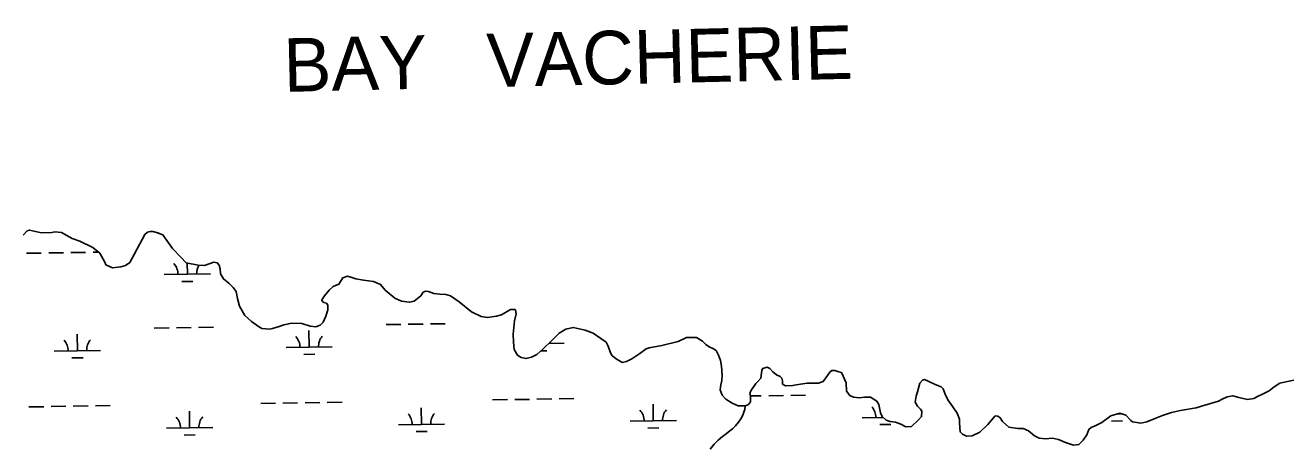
# Model space of a CAD drawing. Extents: x 3812694 to 3850888, y 319753 to 345638.
# Drawn here: x 3822925 to 3825660, y 332970 to 333885 of the extents above; entities that cross this region are included whole.
import ezdxf

# ---------------------------------------------------------------- set-up
doc = ezdxf.new("R2010")
doc.units = 0
for name, color, linetype in [('V-RIVR-IDEN', 7, 'Continuous'), ('V-TOPO-SHOR', 7, 'Continuous'), ('V-WETL-SWMP', 7, 'Continuous')]:
    doc.layers.add(name, color=color, linetype=linetype)

msp = doc.modelspace()

# ---------------------------------------------------------------- linework, layer by layer
at = {"layer": 'V-TOPO-SHOR'}
for points in [[(3823704.4, 333311.1), (3823694.2, 333323.5), (3823679.2, 333330.3), (3823657.3, 333332.5), (3823640.9, 333335.9), (3823630, 333339.4), (3823622.4, 333341.5), (3823612.2, 333338.1), (3823603.9, 333324.4), (3823591.6, 333319), (3823582.7, 333311.5), (3823573, 333299.2), (3823566.9, 333290.3), (3823568.2, 333286.9), (3823571.6, 333284.8), (3823577.1, 333282.8), (3823579.8, 333278.7), (3823579.8, 333268.4), (3823575.6, 333254.7), (3823570.1, 333241.7), (3823563.3, 333235.6), (3823553.7, 333231.5), (3823542, 333232.9), (3823523.6, 333239.1), (3823502.4, 333239.9), (3823484.6, 333235.8), (3823475, 333232.4), (3823459.9, 333228.4), (3823454.4, 333227), (3823437.3, 333228.5), (3823429.8, 333232.6), (3823414.8, 333243.6), (3823400.5, 333256.6), (3823388.9, 333276.5), (3823384.2, 333292.9), (3823381.5, 333308), (3823375.4, 333316.9), (3823366.5, 333325.8), (3823354.2, 333335.5), (3823347.4, 333346.4), (3823346.7, 333357.4), (3823344.7, 333365.6), (3823340.6, 333370.4), (3823333.1, 333371.8), (3823313.2, 333364.3), (3823299.6, 333365), (3823273.6, 333370.6), (3823262, 333382.3), (3823243.6, 333401.5), (3823223.1, 333431), (3823209.4, 333435.8), (3823201.2, 333437.9), (3823195.1, 333437.9), (3823189.6, 333436.5), (3823184.1, 333431.8), (3823161.4, 333390.1), (3823151.1, 333371), (3823142.2, 333364.8), (3823131.9, 333361.5), (3823114.1, 333359.5), (3823099.8, 333366.3), (3823097, 333371.8), (3823086.8, 333391), (3823071.1, 333403.4), (3823043.1, 333417.2), (3823026.7, 333423.4), (3823015.1, 333429.6), (3823003.5, 333436.4), (3822989.1, 333437.2), (3822982.3, 333435.8), (3822960.4, 333435.2), (3822934.4, 333441.4), (3822928.9, 333439.4), (3822920.7, 333430.5)], [(3824666.6, 333133.7), (3824661.8, 333126.2), (3824652.2, 333113.2), (3824641.9, 333109.8), (3824617.3, 333109.9), (3824594, 333106.5), (3824586.5, 333104.5), (3824570.7, 333103.9), (3824564.6, 333108), (3824564.6, 333114.8), (3824562.6, 333121), (3824559.2, 333124.4), (3824551, 333127.9), (3824543.5, 333134), (3824536.6, 333141.6), (3824531.2, 333144.3), (3824521.6, 333141.6), (3824519.5, 333138.2), (3824518.8, 333131.4), (3824517.4, 333120.4), (3824511.2, 333113.6), (3824506.4, 333108.8), (3824495.4, 333093.1), (3824493.4, 333087.7), (3824494.7, 333082.2), (3824494.7, 333080.8), (3824494.7, 333069.2), (3824490.6, 333063.7), (3824483.7, 333061), (3824468.6, 333060.4), (3824455, 333066.6), (3824441.3, 333075.5), (3824433.8, 333083.8), (3824429.1, 333095.4), (3824430.5, 333106.3), (3824432.6, 333115.9), (3824433.3, 333126.9), (3824432, 333146.7), (3824430, 333159), (3824425.9, 333170.7), (3824420.4, 333180.3), (3824415, 333184.4), (3824405.4, 333188.5), (3824398.6, 333193.3), (3824391.1, 333200.9), (3824378.1, 333208.5), (3824356.2, 333208.5), (3824338.4, 333199.7), (3824302.8, 333191.6), (3824275.4, 333186.2), (3824269.2, 333184.2), (3824255.5, 333173.9), (3824238.4, 333162.4), (3824226.7, 333156.9), (3824217.8, 333154.9), (3824208.3, 333159.7), (3824195.3, 333169.3), (3824191.9, 333175.5), (3824187.1, 333189.9), (3824182.4, 333198.8), (3824170.8, 333206.4), (3824154.4, 333218), (3824137.3, 333224.9), (3824111.3, 333230.5), (3824094.9, 333227.1), (3824080.5, 333218.3), (3824064, 333201.2), (3824046.2, 333184.2), (3824032.5, 333171.9), (3824020.8, 333166.4), (3824009.2, 333163.1), (3823998.2, 333165.1), (3823990.7, 333170.6), (3823983.2, 333183), (3823981.9, 333198.7), (3823981.3, 333215.8), (3823982.7, 333230.2), (3823984.1, 333244.6), (3823987.6, 333260.3), (3823986.2, 333267.8), (3823985.5, 333269.2), (3823975.3, 333269.2), (3823956.1, 333257.7), (3823945.1, 333254.9), (3823926, 333252.3), (3823911.6, 333254.4), (3823891.1, 333264), (3823864.5, 333286), (3823845.4, 333299), (3823835.8, 333301.8), (3823822.8, 333302.5), (3823809.8, 333303.9), (3823798.2, 333308.1), (3823792, 333308.8), (3823786.5, 333306.8), (3823781, 333298.6), (3823766.6, 333287.7), (3823757.1, 333284.9), (3823739.3, 333287.1), (3823724.9, 333293.9), (3823704.4, 333311.1)], [(3825671, 333116.2), (3825653.9, 333112.8), (3825640.9, 333109.5), (3825628.5, 333102), (3825617.6, 333093.1), (3825603.2, 333086.3), (3825593.6, 333081.5), (3825584.7, 333076.8), (3825571, 333074.8), (3825551.8, 333078.9), (3825538.9, 333082.4), (3825527.2, 333080.4), (3825516.3, 333074.9), (3825508, 333070.9), (3825478.6, 333062.1), (3825459.4, 333056.6), (3825425.9, 333050.6), (3825406, 333046.5), (3825386.8, 333039.8), (3825372.4, 333034.3), (3825352.6, 333026.2), (3825340.2, 333023.5), (3825321.8, 333026.3), (3825318.4, 333029), (3825307.5, 333040.7), (3825294.5, 333044.8), (3825275.3, 333039.4), (3825255.4, 333024.4), (3825241, 333017.6), (3825232.1, 333013.6), (3825227.3, 333009.5), (3825223.2, 332997.8), (3825214.9, 332986.2), (3825206, 332976.7), (3825194.4, 332975.4), (3825176.6, 332981.6), (3825161.6, 332987.8), (3825148.6, 332990.5), (3825133.5, 332989.2), (3825119.8, 332990.6), (3825109.6, 332995.5), (3825096.6, 333006.4), (3825085, 333012), (3825074, 333012), (3825054.2, 333014.8), (3825040.6, 333026.5), (3825035.1, 333034.7), (3825030.3, 333038.1), (3825024.9, 333038.8), (3825008.4, 333020.4), (3824991.2, 333004), (3824974.8, 332995.9), (3824962.5, 332995.2), (3824953.6, 332999.4), (3824948.8, 333004.2), (3824947.5, 333024), (3824947.5, 333032.2), (3824942.1, 333044.6), (3824933.2, 333058.3), (3824922.3, 333074), (3824916.2, 333085.7), (3824912.1, 333097.3), (3824907.4, 333102.1), (3824894.4, 333107), (3824879.4, 333114.5), (3824871.8, 333118), (3824867, 333116.6), (3824861.5, 333109.8), (3824856.7, 333091.3), (3824853.9, 333081.8), (3824851.8, 333068.8), (3824856.6, 333059.9), (3824862.7, 333053.7), (3824866.2, 333048.9), (3824865.4, 333037.3), (3824858.6, 333030.4), (3824843.5, 333016.1), (3824831.2, 333015.5), (3824820.2, 333021), (3824808.6, 333025.1), (3824797, 333026.5), (3824788.8, 333030), (3824779.9, 333037.5), (3824776.5, 333045.7), (3824772.5, 333063.6), (3824768.4, 333071.1), (3824754.7, 333079.3), (3824741.7, 333079.4), (3824730.8, 333078), (3824717.8, 333079.5), (3824710.2, 333082.9), (3824702.8, 333092.5), (3824702.1, 333110.3), (3824691.9, 333132.9), (3824686.5, 333134.3), (3824677.6, 333137.1), (3824670.7, 333137.1), (3824666.6, 333133.7)], [(3824483.7, 333061), (3824482.8, 333053), (3824481.6, 333049), (3824479.9, 333044.9), (3824478.1, 333040.7), (3824474.2, 333032.9), (3824469, 333025.1), (3824462.7, 333017.2), (3824455.9, 333010.8), (3824450.5, 333006.4), (3824442.6, 333000.4), (3824434.3, 332994.3), (3824425.1, 332986.4), (3824416.1, 332977.5), (3824407.8, 332967)]]:
    msp.add_lwpolyline(points, dxfattribs=at)
at = {"layer": 'V-WETL-SWMP'}
for p, q in [((3822927.8, 333391.1), (3822959.8, 333391.6)), ((3822975.8, 333391.8), (3823007.8, 333392.3)), ((3823023.8, 333392.5), (3823055.8, 333393)), ((3823071.8, 333393.3), (3823083.8, 333393.4)), ((3823275.9, 333345.6), (3823275.5, 333370.2)), ((3823225.9, 333344.8), (3823325.9, 333346.4)), ((3823264.1, 333330), (3823288.1, 333330.3)), ((3823037.9, 333180.1), (3823037.3, 333216.1)), ((3823204.2, 333229.1), (3823236.2, 333229.6)), ((3823252.2, 333229.8), (3823284.2, 333230.3)), ((3823300.2, 333230.5), (3823332.2, 333231)), ((3823539.7, 333187.7), (3823539.2, 333223.7)), ((3823706.1, 333236.7), (3823738.1, 333237.1)), ((3823754.1, 333237.4), (3823786.1, 333237.9)), ((3823802.1, 333238.1), (3823834.1, 333238.6)), ((3823489.7, 333187), (3823589.7, 333188.5)), ((3824058.1, 333195.6), (3824091.6, 333196.1)), ((3822987.9, 333179.4), (3823087.9, 333180.9)), ((3823026.1, 333164.5), (3823050.1, 333164.9)), ((3823528, 333172.1), (3823552, 333172.5)), ((3824041.4, 333179.9), (3824053.8, 333180.1)), ((3824080.5, 333075.8), (3824112.5, 333076.3)), ((3824494.7, 333082.1), (3824518.4, 333082.4)), ((3824534.4, 333082.7), (3824566.4, 333083.2)), ((3824582.4, 333083.4), (3824614.4, 333083.9)), ((3822932.9, 333058.4), (3822964.9, 333058.9)), ((3822980.9, 333059.2), (3823012.9, 333059.7)), ((3823028.9, 333059.9), (3823060.9, 333060.4)), ((3823076.8, 333060.6), (3823108.8, 333061.1)), ((3823280.9, 333013), (3823280.4, 333049)), ((3823434.7, 333066), (3823466.7, 333066.5)), ((3823482.7, 333066.8), (3823514.7, 333067.2)), ((3823530.7, 333067.5), (3823562.7, 333068)), ((3823578.7, 333068.2), (3823610.7, 333068.7)), ((3823782.8, 333020.6), (3823782.2, 333056.5)), ((3823936.6, 333073.6), (3823968.6, 333074.1)), ((3823984.6, 333074.4), (3824016.6, 333074.8)), ((3824032.6, 333075.1), (3824064.6, 333075.6)), ((3824284.6, 333028.1), (3824284.1, 333064.1)), ((3823732.8, 333019.8), (3823832.8, 333021.3)), ((3824234.6, 333027.4), (3824334.6, 333028.9)), ((3824736.5, 333035), (3824782.1, 333035.7)), ((3825276.5, 333027.7), (3825300.5, 333028.1)), ((3825289.2, 333043.3), (3825298.7, 333043.5)), ((3823230.9, 333012.2), (3823330.9, 333013.7)), ((3823269.1, 332997.3), (3823293.1, 332997.7)), ((3823771, 333004.9), (3823795, 333005.3)), ((3824272.8, 333012.5), (3824296.8, 333012.9)), ((3824774.7, 333020.1), (3824798.7, 333020.5))]:
    msp.add_line(p, q, dxfattribs=at)
for points in [[(3822920.7, 333430.5), (3822928.9, 333439.4), (3822934.4, 333441.4), (3822960.4, 333435.2), (3822982.3, 333435.8), (3822989.1, 333437.2), (3823003.5, 333436.4), (3823015.1, 333429.6), (3823026.7, 333423.4), (3823043.1, 333417.2), (3823071.1, 333403.4), (3823086.8, 333391), (3823097, 333371.8), (3823099.8, 333366.3), (3823114.1, 333359.5), (3823131.9, 333361.5), (3823142.2, 333364.8), (3823151.1, 333371), (3823161.4, 333390.1), (3823184.1, 333431.8), (3823189.6, 333436.5), (3823195.1, 333437.9), (3823201.2, 333437.9), (3823209.5, 333435.8), (3823223.1, 333431), (3823243.6, 333401.5), (3823262, 333382.3), (3823273.6, 333370.6), (3823299.6, 333365), (3823313.2, 333364.3), (3823333.1, 333371.8), (3823340.6, 333370.4), (3823344.7, 333365.6), (3823346.7, 333357.4), (3823347.4, 333346.4), (3823354.2, 333335.5), (3823366.5, 333325.8), (3823375.4, 333316.9), (3823381.5, 333308)], [(3823381.5, 333308), (3823384.2, 333292.9), (3823388.9, 333276.5), (3823400.5, 333256.6), (3823414.8, 333243.6), (3823429.8, 333232.6), (3823437.3, 333228.5), (3823454.4, 333227), (3823459.9, 333228.4), (3823475, 333232.4), (3823484.6, 333235.8), (3823502.4, 333239.9), (3823523.6, 333239.1), (3823542, 333232.9), (3823553.7, 333231.5), (3823563.3, 333235.6), (3823570.1, 333241.7), (3823575.6, 333254.7), (3823579.8, 333268.4), (3823579.8, 333278.7), (3823577.1, 333282.8), (3823571.6, 333284.8), (3823568.2, 333286.9), (3823566.9, 333290.3), (3823573, 333299.2), (3823582.7, 333311.5), (3823591.6, 333319), (3823603.9, 333324.4), (3823612.2, 333338.1), (3823622.4, 333341.5), (3823630, 333339.4), (3823640.9, 333335.9), (3823657.3, 333332.5), (3823679.2, 333330.3), (3823694.2, 333323.5), (3823704.4, 333311.1), (3823724.9, 333293.9), (3823739.3, 333287.1), (3823757.1, 333284.9), (3823766.6, 333287.7), (3823781, 333298.6), (3823786.5, 333306.8), (3823792, 333308.8), (3823798.2, 333308.1), (3823809.8, 333303.9), (3823822.8, 333302.5), (3823835.8, 333301.8), (3823845.4, 333299), (3823864.5, 333286), (3823891.1, 333264), (3823911.6, 333254.4), (3823926, 333252.3), (3823945.1, 333254.9), (3823956.1, 333257.7), (3823975.3, 333269.2), (3823985.5, 333269.2), (3823986.2, 333267.8), (3823987.6, 333260.3), (3823984.1, 333244.6), (3823982.7, 333230.2), (3823981.3, 333215.8), (3823981.9, 333198.7), (3823983.2, 333183), (3823990.7, 333170.6), (3823998.2, 333165.1), (3824009.2, 333163.1), (3824020.8, 333166.4), (3824032.5, 333171.9), (3824046.2, 333184.2), (3824064, 333201.2), (3824080.5, 333218.3), (3824094.9, 333227.1), (3824111.3, 333230.5), (3824137.3, 333224.9), (3824154.4, 333218), (3824170.8, 333206.4), (3824182.4, 333198.8), (3824187.1, 333189.9), (3824191.9, 333175.5), (3824195.3, 333169.3), (3824208.3, 333159.7), (3824217.8, 333154.9), (3824226.7, 333156.9), (3824238.4, 333162.4), (3824255.5, 333173.9), (3824269.2, 333184.2), (3824275.4, 333186.2), (3824302.8, 333191.6), (3824338.4, 333199.7), (3824356.2, 333208.5), (3824378.1, 333208.5), (3824391.1, 333200.9), (3824398.6, 333193.3), (3824405.4, 333188.5), (3824415, 333184.4), (3824420.4, 333180.3), (3824425.9, 333170.7), (3824430, 333159), (3824432, 333146.7), (3824433.3, 333126.9), (3824432.6, 333115.9)], [(3824432.6, 333115.9), (3824430.5, 333106.3), (3824429.1, 333095.4), (3824433.8, 333083.8), (3824441.3, 333075.5), (3824455, 333066.6), (3824468.6, 333060.4), (3824483.7, 333061), (3824490.6, 333063.7), (3824494.7, 333069.2), (3824494.7, 333080.8), (3824494.7, 333082.2), (3824493.4, 333087.7), (3824495.4, 333093.1), (3824506.4, 333108.8), (3824511.2, 333113.6), (3824517.4, 333120.4), (3824518.8, 333131.4), (3824519.5, 333138.2), (3824521.6, 333141.6), (3824531.2, 333144.4), (3824536.6, 333141.6), (3824543.5, 333134), (3824551, 333127.9), (3824559.2, 333124.4), (3824562.6, 333121), (3824564.6, 333114.8), (3824564.6, 333108), (3824570.7, 333103.9), (3824586.5, 333104.5), (3824594, 333106.5), (3824617.3, 333109.9), (3824641.9, 333109.8), (3824652.2, 333113.2), (3824661.8, 333126.2), (3824666.6, 333133.7), (3824670.7, 333137.1), (3824677.6, 333137.1), (3824686.5, 333134.3), (3824691.9, 333132.9), (3824702.1, 333110.3), (3824702.8, 333092.5), (3824710.3, 333082.9), (3824717.8, 333079.5), (3824730.8, 333078), (3824741.7, 333079.4), (3824754.7, 333079.3), (3824768.4, 333071.1), (3824772.5, 333063.6), (3824776.5, 333045.7), (3824779.9, 333037.5), (3824788.8, 333030), (3824797, 333026.5), (3824808.6, 333025.1), (3824820.2, 333021), (3824831.2, 333015.5), (3824843.5, 333016.1), (3824858.6, 333030.4), (3824865.4, 333037.3), (3824866.2, 333048.9), (3824862.7, 333053.7), (3824856.6, 333059.9), (3824851.8, 333068.8), (3824853.9, 333081.8), (3824856.7, 333091.3), (3824861.5, 333109.8), (3824867, 333116.6), (3824871.8, 333118), (3824879.4, 333114.5), (3824894.4, 333107), (3824907.4, 333102.1), (3824912.1, 333097.3), (3824916.2, 333085.7), (3824922.3, 333074), (3824933.2, 333058.3), (3824942.1, 333044.6), (3824947.5, 333032.2), (3824947.5, 333024), (3824948.8, 333004.2), (3824953.6, 332999.4), (3824962.5, 332995.2), (3824974.8, 332995.9), (3824991.2, 333004), (3825008.4, 333020.4), (3825024.9, 333038.8), (3825030.3, 333038.1), (3825035.1, 333034.7), (3825040.6, 333026.5), (3825054.2, 333014.8), (3825074, 333012), (3825085, 333012), (3825096.6, 333006.4), (3825109.6, 332995.5), (3825119.8, 332990.6), (3825133.5, 332989.2), (3825148.6, 332990.5), (3825161.6, 332987.8), (3825176.6, 332981.6), (3825194.4, 332975.4), (3825206, 332976.7), (3825214.9, 332986.2)], [(3825214.9, 332986.2), (3825223.2, 332997.8), (3825227.3, 333009.5), (3825232.1, 333013.6), (3825241, 333017.6), (3825255.4, 333024.4), (3825275.3, 333039.4), (3825294.5, 333044.8), (3825307.5, 333040.7), (3825318.4, 333029), (3825321.8, 333026.3), (3825340.2, 333023.5), (3825352.6, 333026.2), (3825372.4, 333034.3), (3825386.8, 333039.8), (3825406, 333046.5), (3825425.9, 333050.6), (3825459.4, 333056.6), (3825478.6, 333062.1), (3825508, 333070.9), (3825516.3, 333074.9), (3825527.2, 333080.4), (3825538.9, 333082.4), (3825551.8, 333078.9), (3825571, 333074.8), (3825584.7, 333076.8), (3825593.6, 333081.5), (3825603.2, 333086.3), (3825617.6, 333093.1), (3825628.5, 333102), (3825640.9, 333109.5), (3825653.9, 333112.8), (3825671, 333116.2)]]:
    msp.add_lwpolyline(points, dxfattribs=at)
for centre, start, end in [((3823220.6, 333345.2), 0.0949, 41.6385), ((3823331.1, 333346.9), 149.1604, 181.6385), ((3822982.6, 333179.8), 0.0949, 41.6385), ((3823093.1, 333181.4), 140.0949, 181.6385), ((3823484.5, 333187.3), 0.0949, 41.6385), ((3823595, 333189), 140.0949, 181.6385), ((3824096.8, 333196.6), 176.2064, 181.6385), ((3824229.4, 333027.8), 0.0949, 41.6385), ((3824339.8, 333029.5), 140.0949, 181.6385), ((3824731.2, 333035.4), 0.0949, 41.6385), ((3823225.7, 333012.6), 0.0949, 41.6385), ((3823336.1, 333014.3), 140.0949, 181.6385), ((3823727.5, 333020.2), 0.0949, 41.6385), ((3823838, 333021.9), 140.0949, 181.6385)]:
    msp.add_arc(centre, 35.2, start, end, dxfattribs=at)

# ---------------------------------------------------------------- texts
at = {"layer": 'V-RIVR-IDEN'}
msp.add_text('BAY   VACHERIE', height=116, rotation=1.3324, dxfattribs=at).set_placement((3823485.3, 333740.4))

doc.saveas('drawing.dxf')
